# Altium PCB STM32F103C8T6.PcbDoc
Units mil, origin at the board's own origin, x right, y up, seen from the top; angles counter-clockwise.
Board outline 2362.2 x 2362.2 mil, 2 copper layers (Top Layer, Bottom Layer); 70 components, 56 nets, 271 pads, 82 vias.
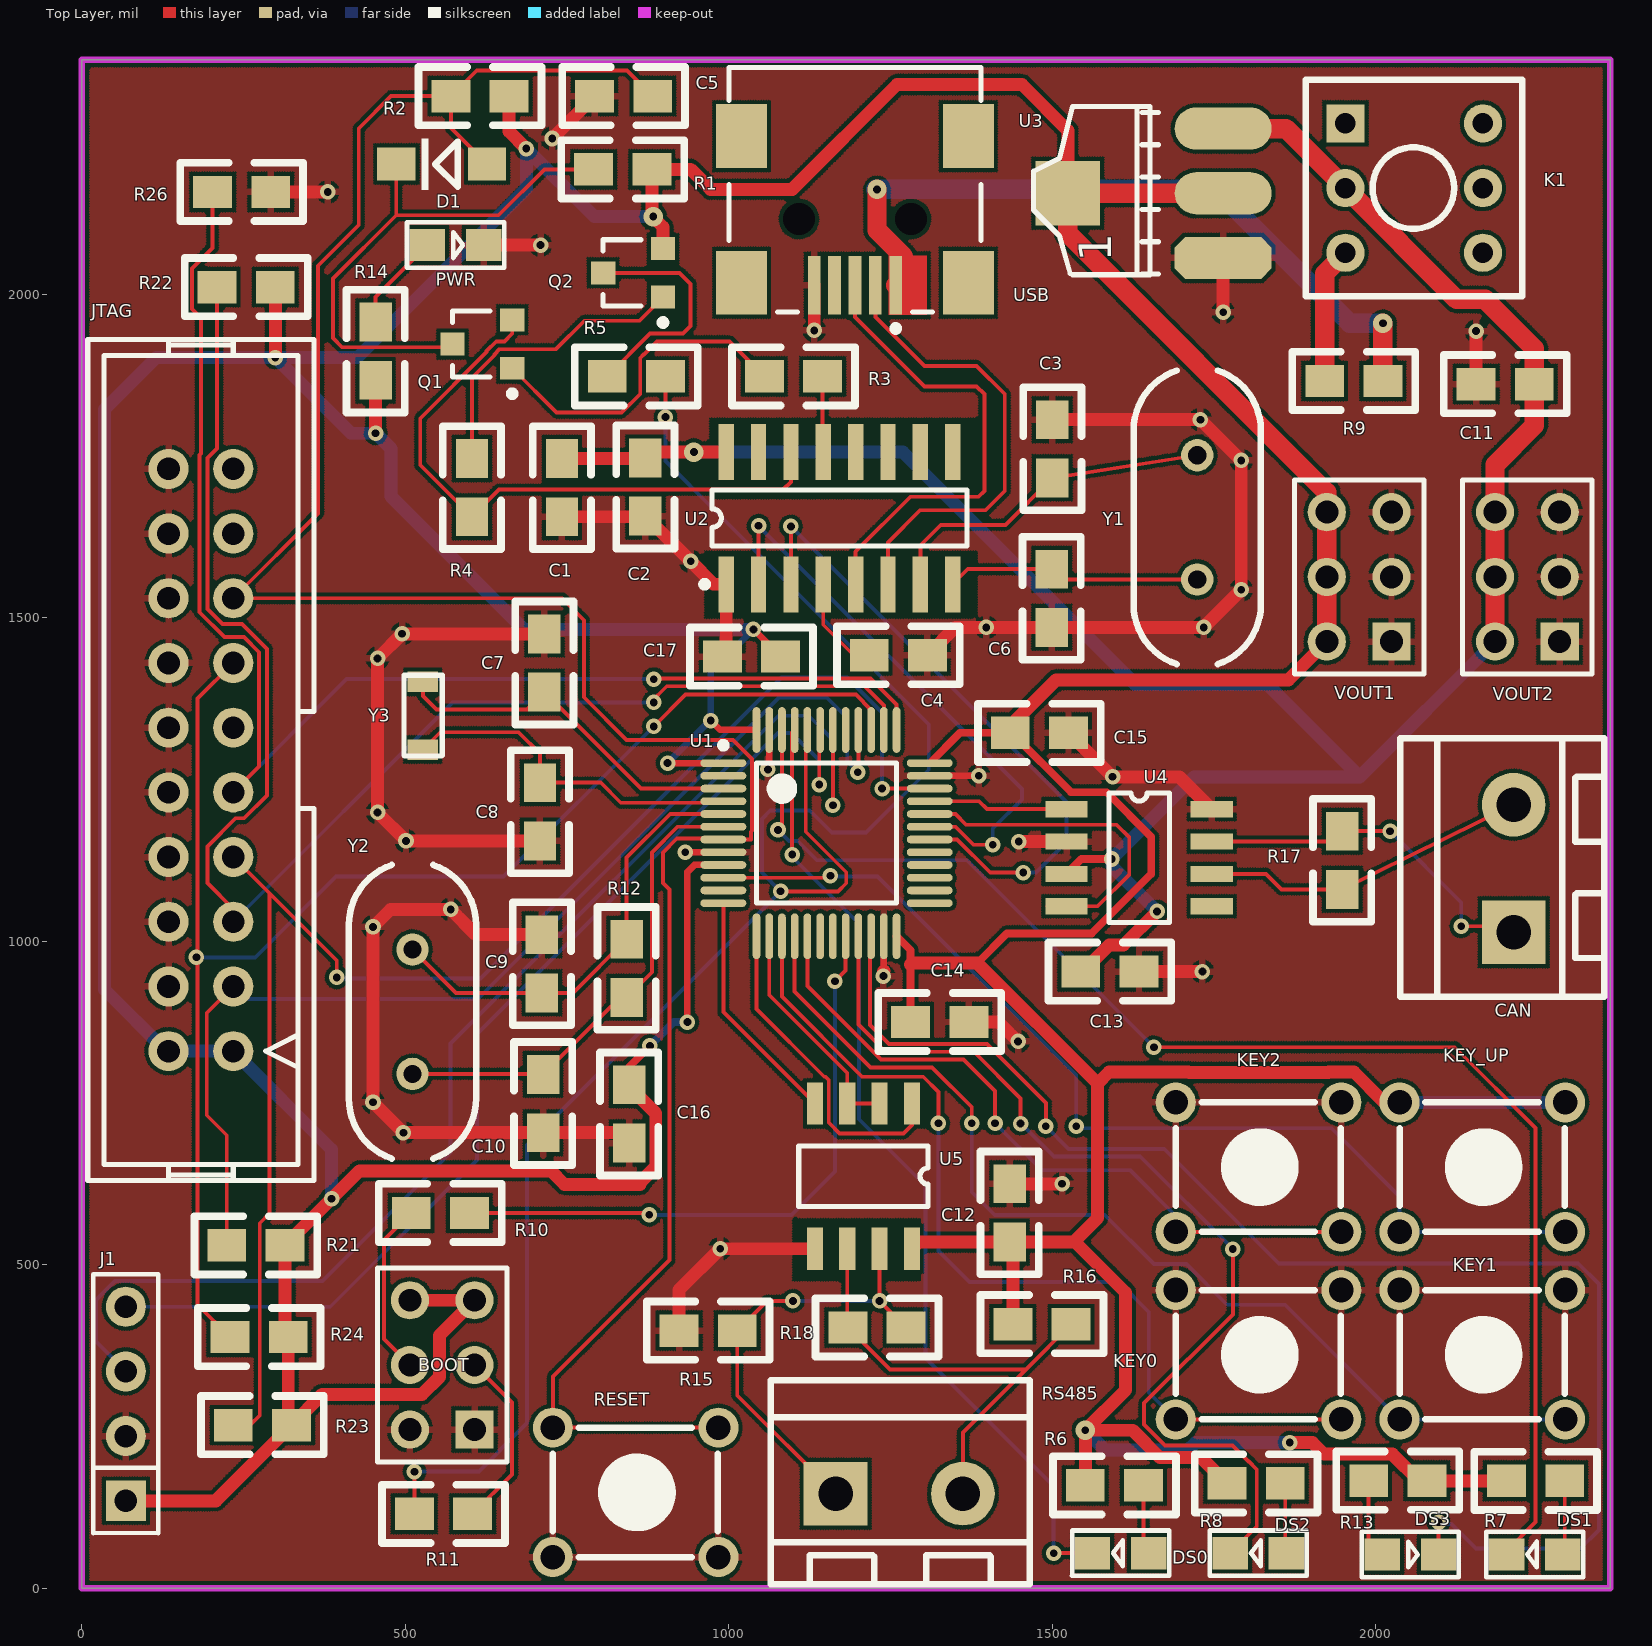
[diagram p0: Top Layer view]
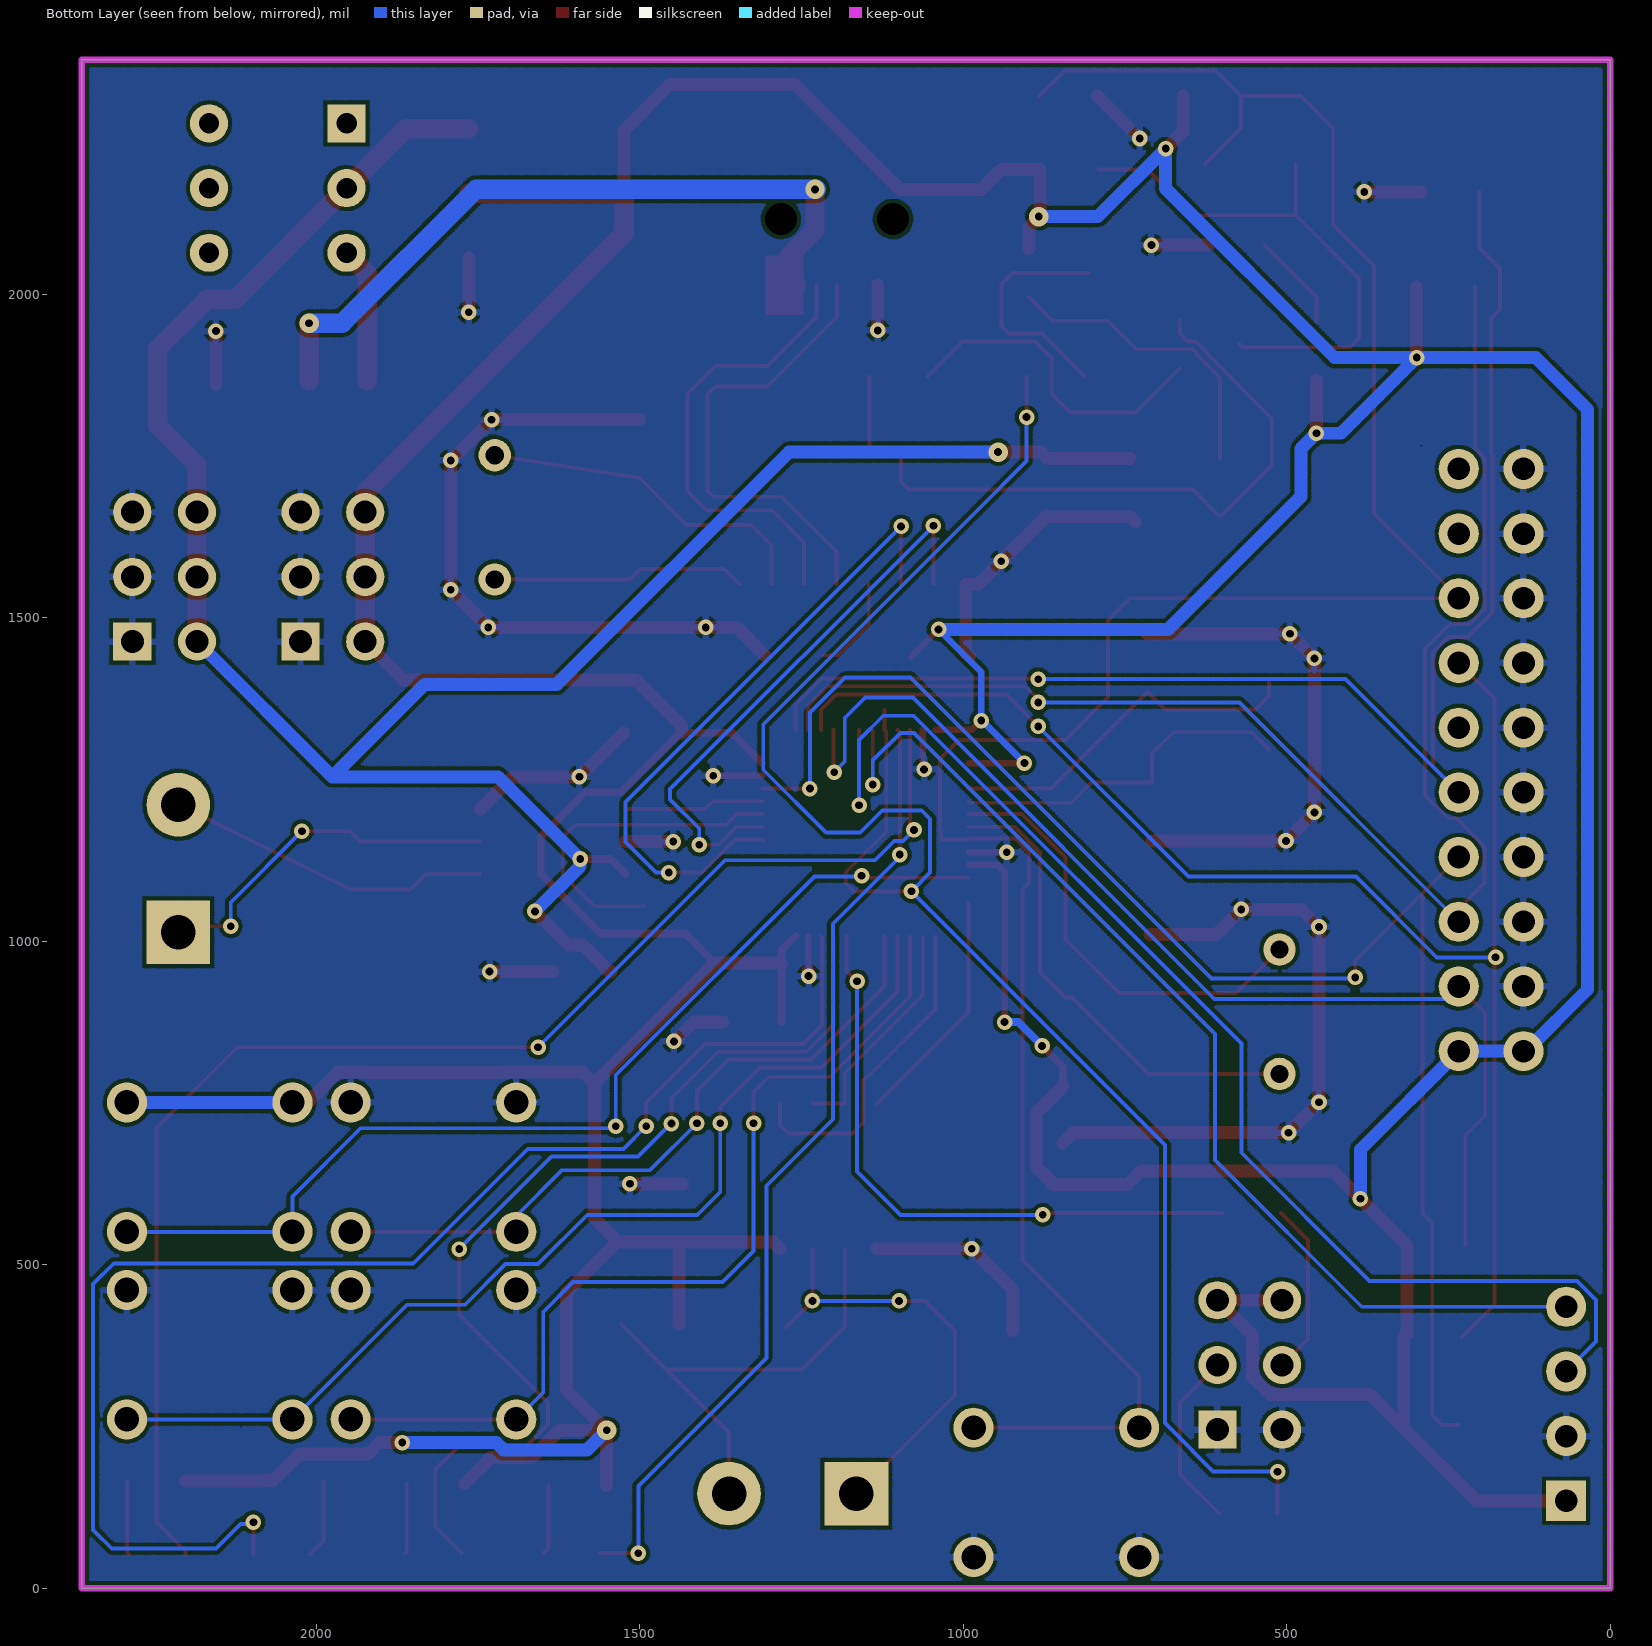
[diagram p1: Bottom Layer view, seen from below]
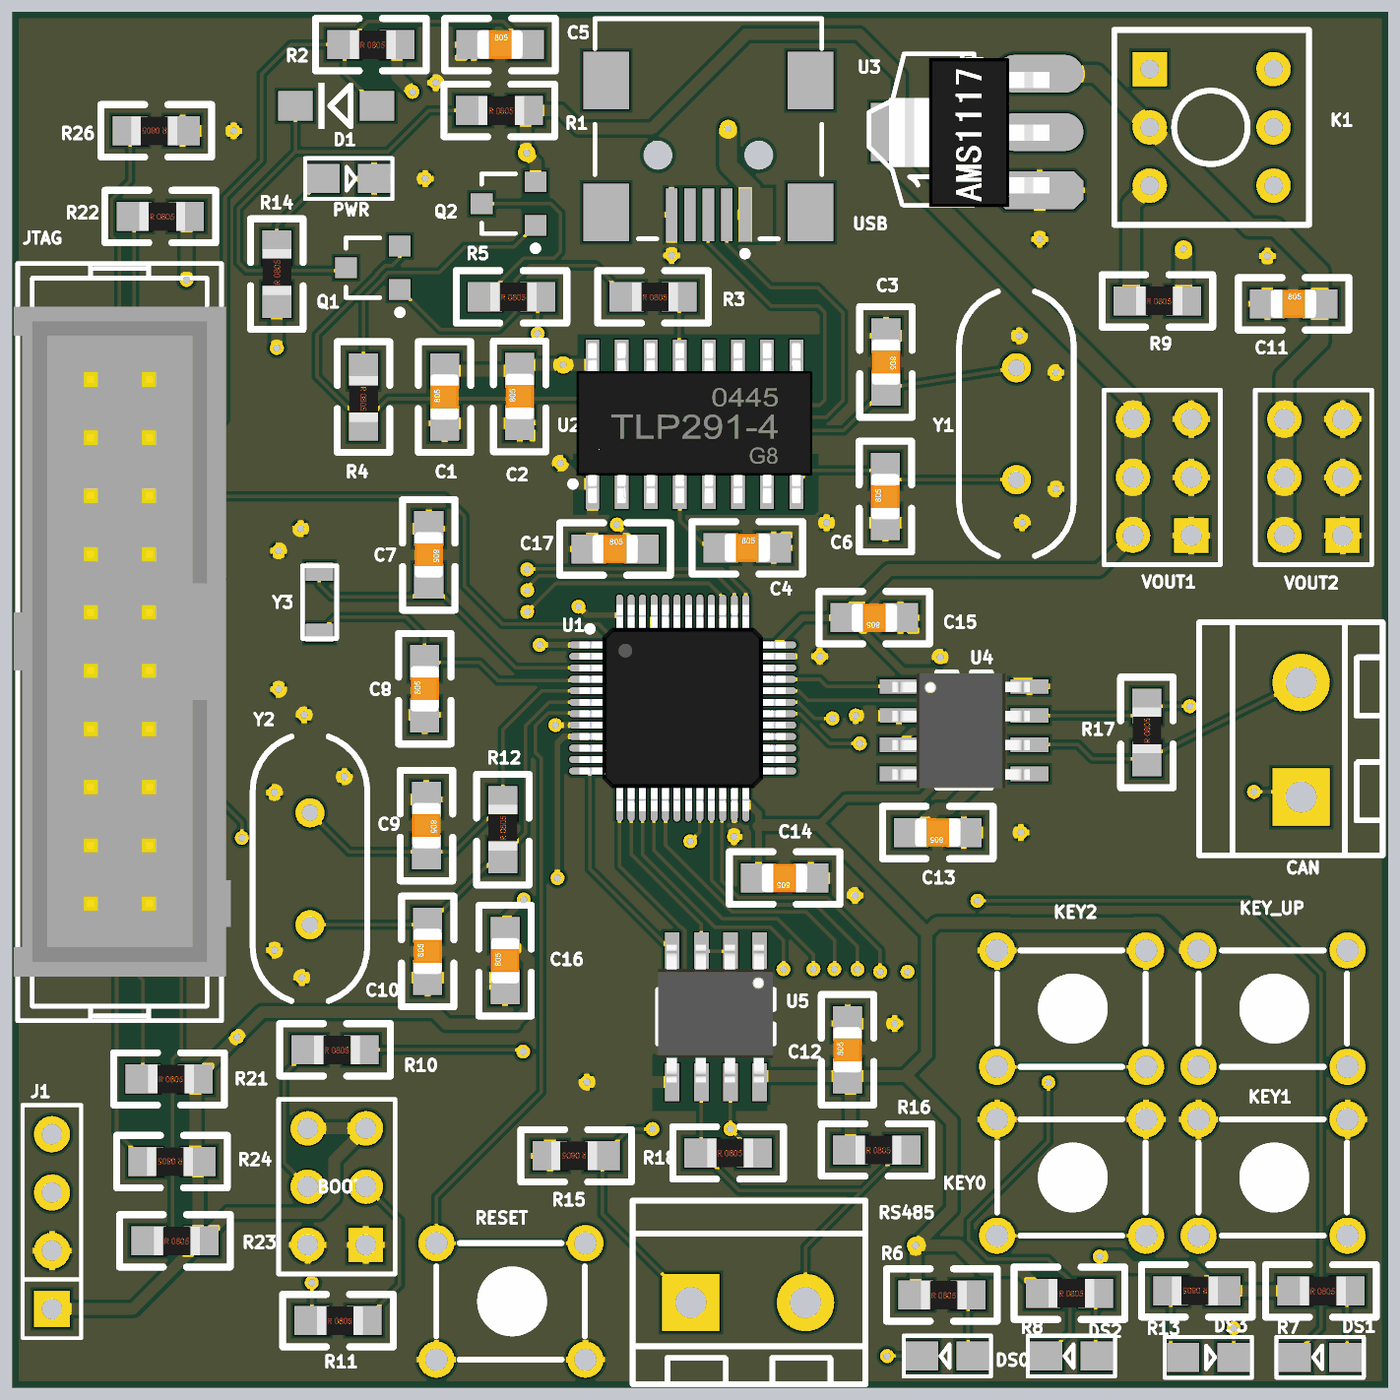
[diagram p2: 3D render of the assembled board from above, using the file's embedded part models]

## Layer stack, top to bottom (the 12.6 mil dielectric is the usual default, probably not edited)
Top Layer: signal copper 1.4
Dielectric: dielectric 12.6, FR-4, Dk 4.8
Bottom Layer: signal copper 1.4

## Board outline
0,0 2362.2,0 2362.2,2362.2 0,2362.2

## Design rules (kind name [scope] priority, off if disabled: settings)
Clearance [All] p1: gap=6
DiffPairsRouting [All] p1: maxlimit=6 minlimit=6 mostfreqgap=6 maxuncoupledlength=500
HoleToHoleClearance [All] p1: gap=5 allowstackedmicrovias=TRUE
MinimumSolderMaskSliver [All] p1: minsoldermaskwidth=2
PolygonConnect [All] p1: connectstyle=Relief reliefconductorwidth=10 reliefentries=4 polygonreliefangle="90 Angle"
RoutingVias [All] p1: holewidth=12 width=24 viastyle="Through Hole" minholewidth=12 minwidth=24 maxholewidth=12 maxwidth=24
SMDNeckDown [All] p1: percent=100.000
SilkToSilkClearance [All] p1: silktosilkclearance=2
SilkscreenOverComponentPads [All] p1: minsilkscreentomaskgap=2
SolderMaskExpansion [All] p1: expansion=2.5
Width PWR [InNetClass('PWR')] p1: maxlimit=60 minlimit=10 preferedwidth=10
Width [All] p2: maxlimit=6 minlimit=6 preferedwidth=6
23 further rules are at their usual default settings.

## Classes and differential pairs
net class GND: GND
net class PWR: GND VCC3.3 VCC5 VUSB

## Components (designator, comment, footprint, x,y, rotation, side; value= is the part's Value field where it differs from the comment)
BOOT "Header 3X2" HDR2X3 607,245 r90 top
C1 "Cap" 0805 742,1656 r90 top
C2 "Cap" 0805 871,1657 r90 top
C3 "Cap" 0805 1500,1806 r270 top
C4 "Cap" 0805 1217,1442 r0 top
C5 "Cap" 0805 792.41,2306.15 r0 top
C6 "Cap" 0805 1499,1485 r90 top
C7 "Cap" 0805 715,1475 r270 top
C8 "Cap" 0805 708,1155 r90 top
C9 "Cap" 0805 711,1010 r270 top
C10 "Cap" 0805 713,704 r90 top
C11 "Cap" 0805 2155,1861 r0 top
C12 "Cap" 0805 1434,535 r90 top
C13 "Cap" 0805 1634,953 r180 top
C14 "Cap" 0805 1371,875 r180 top
C15 "Cap" 0805 1525,1322 r180 top
C16 "Cap" 0805 846,688 r90 top
C17 "Cap" 0805 990,1440 r0 top
CAN "CAN" HEAD2L-0.8 2213,1014 r90 top
D1 "1N4148" DIODE_SOP 626,2201 r180 top
DS0 "LED1" SMDLED 1649,54 r180 top
DS1 "LED1" SMDLED 2289,52 r180 top
DS2 "LED1" SMDLED 1862,54 r180 top
DS3 "LED1" SMDLED 2010,52 r0 top
J1 "OLED_MODBLE" HEAD4 68,135 r90 top
JTAG "JTAG" JTAG_20 184,1280 r90 top
K1 "BUTTON" BTN8.5*8.5 1953,2264 r0 top
KEY0 "KEY_M" KEY_M 1690.83,460.76 r0 top
KEY1 "KEY_M" KEY_M 2036.73,460.76 r0 top
KEY2 "KEY_M" KEY_M 1690.83,750.76 r0 top
KEY_UP "KEY_M" KEY_M 2036.73,750.76 r0 top
PWR "LED1" SMDLED 534,2076 r0 top
Q1 "S8050" SOT-23R 624,1923 r90 top
Q2 "S8550" SOT-23R 857,2033 r90 top
R1 "Res2" R0805 791,2192.94 r0 top
R2 "Res2" R0805 570.41,2306.09 r0 top
R3 "Res2" R0805 1055,1872.94 r0 top
R4 "Res2" R0805 602.94,1746 r270 top
R5 "Res2" R0805 812,1872.94 r0 top
R6 "Res2" R0805 1551,158.94 r0 top
R7 "Res2" R0805 2202,165.94 r0 top
R8 "Res2" R0805 1770,161.94 r0 top
R9 "Res2" R0805 1921,1865.94 r0 top
R10 "Res2" R0805 509,579.94 r0 top
R11 "Res2" R0805 514,114.94 r0 top
R12 "Res2" R0805 842.06,913 r90 top
R13 "Res2" R0805 2079,166.06 r180 top
R14 "Res2" R0805 454.06,1867 r90 top
R15 "Res2" R0805 1013,398.06 r180 top
R16 "Res2" R0805 1439,407.94 r0 top
R17 "Res2" R0805 1948.06,1080 r90 top
R18 "Res2" R0805 1184,402.94 r0 top
R21 "Res2" R0805 224,529.94 r0 top
R22 "Res2" R0805 209,2010.94 r0 top
R23 "Res2" R0805 234,251.94 r0 top
R24 "Res2" R0805 319,388.06 r180 top
R26 "Res2" R0805 292,2158.06 r180 top
RESET "KEY_M" KEY_M 728,248 r0 top
RS485 "RS485" HEAD2L-0.8 1165,146 r0 top
U1 "STM32F103C8T6" LQFP48_N 1151,1167 r0 top
U2 "CH340G" SOP16M 1171,1654 r0 top
U3 "AMS1117-3.3" AMS1117 1764,2056 r90 top
U4 "TJA1050" SOP-8 1522,1204 r0 top
U5 "SP3485" SOP-8 1283,749 r270 top
USB "USB" USB/SM0.8-6H5 1195,2323 r90 top
VOUT1 "Header 3X2" HDR2X3 2024.25,1463.09 r90 top
VOUT2 "Header 3X2" HDR2X3 2284.25,1463.09 r90 top
Y1 "8M" XTAL_US 1724,1559 r90 top
Y2 "8M" XTAL_US 511,987 r270 top
Y3 "32.768k" 32.768K晶振 557,1411 r270 top

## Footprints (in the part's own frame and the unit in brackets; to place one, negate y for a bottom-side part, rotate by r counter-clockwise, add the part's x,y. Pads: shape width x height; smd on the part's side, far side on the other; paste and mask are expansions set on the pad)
32.768K晶振 [mil]
  rect 31.5x47.24 smd: 1(10,-30) 2(115,-30)
  silkscreen extent 0,-59 125,0
0805 [mil]
  rect 60x50 smd: 1(0,-0.06) 2(90,-0.06)
  silkscreen extent -50,-45 140,45, body extent 6,-25 84,25, height 31
AMS1117 [mil]
  oct 65x150 smd: 1(0.03,-0.06)
  oval 65x150 smd: 2(100.03,-0.06) 3(200.03,-0.06)
  rect 100x100 smd: 4(100.03,239.94)
  silkscreen extent -26,100 234,293, body extent -29,-17 227,259, height 73
BTN8.5*8.5 [mm]
  rect 1.5x1.5 hole 0.8: 1(0,0)
  round 1.5 hole 0.8: 2(0,-2.54) 3(0,-5.08) 4(5.4,-5.08) 5(5.4,-2.54) 6(5.4,0)
  silkscreen extent -1.55,-6.79 6.95,1.71
DIODE_SOP [mm]
  rect 1.5x1.3 smd: 1(0,0) 2(3.556,0)
  silkscreen extent 1.14,-1.02 2.56,1.02
HDR2X3 [mm]
  rect 1.5x1.5 hole 0.9: 1(0,0)
  round 1.5 hole 0.9: 2(0,2.54) 3(2.54,0) 4(2.54,2.54) 5(5.08,0) 6(5.08,2.54)
  silkscreen extent -1.27,-1.27 6.35,3.81
HEAD2L-0.8 [mm]
  rect 2.5x2.5 hole 1.35: 1(0,0)
  round 2.5 hole 1.35: 2(5,0)
  silkscreen extent -2.54,-3.56 7.62,4.44
HEAD4 [mil]
  rect 62x62 hole 35: 1(0,0)
  round 62 hole 35: 2(100,0) 3(200,0) 4(300,0)
  silkscreen extent -50,-50 350,51
JTAG_20 [mil]
  round 62 hole 35: 1(-450,-50) 2(-450,50) 3(-350,-50) 4(-350,50) 5(-250,-50) 6(-250,50) 7(-150,-50) 8(-150,50) 9(-50,-50) 10(-50,50) 11(50,-50) 12(50,50) 13(150,-50) 14(150,50) 15(250,-50) 16(250,50) 17(350,-50) 18(350,50) 19(450,-50) 20(450,50)
  silkscreen extent -650,-175 650,175, body extent -574,-191 576,182, height 350
KEY_M [mil]
  round 62 hole 38: 1(0,0) 1(255.91,0) 2(0,-200) 2(255.91,-200)
  silkscreen extent 0,-200 255,0
LQFP48_N [mm]
  oval 1.8x0.3 smd: 1(-4.05,2.75) 2(-4.05,2.25) 3(-4.05,1.75) 4(-4.05,1.25) 5(-4.05,0.75) 6(-4.05,0.25) 7(-4.05,-0.25) 8(-4.05,-0.75) 9(-4.05,-1.25) 10(-4.05,-1.75) 11(-4.05,-2.25) 12(-4.05,-2.75) 25(4.05,-2.75) 26(4.05,-2.25) 27(4.05,-1.75) 28(4.05,-1.25) 29(4.05,-0.75) 30(4.05,-0.25) 31(4.05,0.25) 32(4.05,0.75) 33(4.05,1.25) 34(4.05,1.75) 35(4.05,2.25) 36(4.05,2.75)
  oval 0.3x1.8 smd: 13(-2.75,-4.05) 14(-2.25,-4.05) 15(-1.75,-4.05) 16(-1.25,-4.05) 17(-0.75,-4.05) 18(-0.25,-4.05) 19(0.25,-4.05) 20(0.75,-4.05) 21(1.25,-4.05) 22(1.75,-4.05) 23(2.25,-4.05) 24(2.75,-4.05) 37(2.75,4.05) 38(2.25,4.05) 39(1.75,4.05) 40(1.25,4.05) 41(0.75,4.05) 42(0.25,4.05) 43(-0.25,4.05) 44(-0.75,4.05) 45(-1.25,4.05) 46(-1.75,4.05) 47(-2.25,4.05) 48(-2.75,4.05)
  silkscreen extent -4.17,-2.75 2.75,3.57, body extent -4.5,-4.5 4.5,4.5, height 1.5
R0805 [mil]
  rect 60x50 smd: 1(0,0) 2(90,0)
  silkscreen extent -50,-45 140,45, body extent 9,-25 88,25, height 15
SMDLED [mm]
  rect 1.4x1.27 smd: 1(0.001,-0.002) 2(2.211,-0.002)
  silkscreen extent -0.8,-0.89 3.01,0.89
SOP16M [mm]
  rect 0.6x2.2 smd: 1(-4.445,-2.6) 2(-3.175,-2.6) 3(-1.905,-2.6) 4(-0.635,-2.6) 5(0.635,-2.6) 6(1.905,-2.6) 7(3.175,-2.6) 8(4.445,-2.6) 9(4.445,2.6) 10(3.175,2.6) 11(1.905,2.6) 12(0.635,2.6) 13(-0.635,2.6) 14(-1.905,2.6) 15(-3.175,2.6) 16(-4.445,2.6)
  silkscreen extent -5.42,-2.72 5,1.1, body extent -5.15,-3.45 5.15,3.55, height 2.1
SOP-8 [mil]
  rect 65x25 smd: 1(0,0) 2(0,-50) 3(0,-100) 4(0,-150) 5(224.41,-150) 6(224.41,-100) 7(224.41,-50) 8(224.41,0)
  silkscreen extent 65,-175 159,25, body extent -11,-174 225,22, height 71
SOT-23R [mm]
  rect 0.9x0.95 smd: 1(0.95,-1.048) 2(-0.95,-1.048) 3(0,1.302)
  silkscreen extent -2.07,-1.17 1.3,1.3
USB/SM0.8-6H5 [mm]
  rect 2.3x0.5 smd: 1(-7.85,-1.6) 2(-7.85,-0.8) 3(-7.85,0) 4(-7.85,0.8) 5(-7.85,1.6)
  rect 2.5x2 smd: 6(-7.75,4.45) 7(-1.996,4.45) 8(-7.75,-4.45) 9(-1.996,-4.45)
  round 0.6 hole 1.27 unplated: MH1(-5.25,2.2) MH2(-5.25,-2.2)
  silkscreen extent -9.67,-4.95 0.7,4.95
XTAL_US [mil]
  round 50 hole 28: 1(0,0) 2(192.13,0)
  silkscreen extent -131,-98 323,98

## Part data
BOOT VOUT1 VOUT2: "Header, 3-Pin, Dua"
C1 C2 C3 C4 C5 C6 C7 C8 C9 C10 C11 C12 C13 C14 C15 C16 C17: "Capacitor"
DS0 DS1 DS2 DS3 PWR: library part LED2, "Typical RED, GREEN, YELLOW, AMBER GaA"
J1: library part OLED_MOD
K1: library part B
Q1: library part NPN, "8050/BCW846/B"
Q2: library part PNP, "8550/"
R1 R2 R3 R4 R5 R6 R7 R8 R9 R10 R11 R12 R13 R14 R15 R16 R17 R18 R21 R22 R23 R24 R26: "Resistor"
U1: library part STM32F10
U2: "USB"
U3: library part AM
U4: library part SN65HV
U5: library part MA
Y1 Y2: library part XTAL, "Crystal Oscil"
Y3: library part XTAL, "Crystal"

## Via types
v1: diameter 24, hole 12, Top Layer to Bottom Layer, 77 vias
v2: diameter 30, hole 12, Top Layer to Bottom Layer, 5 vias

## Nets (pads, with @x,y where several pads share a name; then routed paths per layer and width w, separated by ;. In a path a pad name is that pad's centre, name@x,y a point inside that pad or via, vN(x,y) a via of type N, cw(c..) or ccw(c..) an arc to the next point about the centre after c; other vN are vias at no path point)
BOOT0: R5.2 R11.1 U1.44 | length 2874.7
  Top Layer w6: R11.1 v1(514,180) ; v1(902,1810) R5.2 ; v1(1080,1077) 1169,1077 1181.5,1089.5 1181.5,1106.5 1118.84,1169.16 1118.84,1323.82 U1.44 U1.44@1121.47,1357.37
  Bottom Layer w6: v1(514,180) 613.78,180 645.53,211.74 645.53,212.53 688,255 688,685 v1(1080,1077) 1051,1106 1051,1189 1064,1202 1125,1202 1159,1168 1212,1168 1309,1265 1309,1335 978,1666 902,1742 v1(902,1810)
BOOT1: R10.2 U1.20 | length 968
  Top Layer w6: R10.2 v1@879,579.94 ; v1(1164,938) 1180.53,954.53 U1.20
  Bottom Layer w6: v1@875,575 v1(877,577) 1097,577 1164,644 v1(1164,938)
CAN_RX: U1.32 U4.4 | length 527.3
  Top Layer w6: U1.32 1350.1,1196.53 1366.63,1180 1599,1180 1619,1160 1619,1103 1570,1054 U4.4 U4.4@1492.63,1054
CAN_TX: U1.33 U4.1 | length 216.6
  Top Layer w6: U1.33 1386.79,1216.21 1399,1204 U4.1
CH340_D+: U2.5 USB.3 | length 736.4
  Top Layer w6: USB.3 1195,1964.8 1302.29,1857.5 1383,1857.5 1395,1845.5 1395,1696 1386,1687 1281,1687 1196,1602 U2.5
CH340_D-: U2.6 USB.2 | length 726.4
  Top Layer w6: USB.2 1226.5,1964.8 1302.29,1889 1383,1889 1426.5,1845.5 1426.5,1696 1396.5,1666 1295.5,1666 1246,1616.5 U2.6
GND: BOOT.1 BOOT.2 C1.1 C2.1 C3.1 C4.2 C5.1 C6.1 C7.1 C8.1 C9.1 C10.1 C11.1 C12.2 C13.1 C14.1 C15.1 C16.1 C17.1 J1.2 JTAG.4 JTAG.6 JTAG.8 JTAG.10 JTAG.12 JTAG.14 JTAG.16 JTAG.18 JTAG.20 KEY0.1 KEY1.1 KEY2.1 PWR.2 R15.2 R26.1 RESET.2 U1.8 U1.23 U1.35 U1.47 U2.1 U3.1 U4.2 U4.8 U5.5 USB.5 VOUT1.1 VOUT1.3 VOUT1.5 VOUT2.1 VOUT2.3 VOUT2.5 | length 4911.3
  Top Layer w10: v1(932.47,1137.47) U1.8 ; v1@1058,1263 v1(1060.42,1265.42) 1062.42,1265.42 U1.47 ; v1@1239.58,953.58 U1.23 ; U1.35 v1(1386.42,1255.58)
  Top Layer w20: R26.1 v1(379.94,2158.06) ; PWR.2 v1(708.98,2075.94) ; C8.1@707.94,1155 v1(501,1155) v1(457,1199) v1(457,1437) v1(495,1475) C7.1@715.06,1475 ; C9.1 609,1010 v1(570,1049) 477,1049 v1(450,1022) v1(450,751) v1(497,704) C10.1 830.06,704 C16.1 ; v1(727,2240.68) C5.1 ; C1.1@733.94,1647.87 C1.1 870.06,1656 C2.1 v1(941,1587.06) 976.43,1551.64 U2.1 996,1445.94 C17.1 ; R15.2 923,461 v1(986.59,524.59) U5.5 ; v1(1132.01,1943.99) USB.5 ; v1(1239,946) 1239,953 v1@1239.58,953.58 ; C4.2 1350.06,1485 C6.1 v1(1734,1485) v1(1792,1543) v1(1792,1743) v1(1729,1806) C3.1 ; C14.1 1416.94,875.06 v1(1447,845) ; C12.2 v1(1515,625) v1@1514,626 ; v1(1448,1154) U4.2 ; C15.1 v1(1593.06,1254) 1696.41,1254 U4.8 ; C13.1 v1(1732.06,953.06) ; v1(1764.06,1971.94) U3.1 ; C11.1 v1(2155,1943)
  other v1: 1398,1485
JTCK: JTAG.9 R26.2 U1.37 | length 2176.5
  Top Layer w6: R26.2 202,2071.66 170,2039.66 170,1976.94 184,1962.94 184,1753.54 182,1751.54 182,1508.46 220.46,1470 250.57,1470 274,1446.57 274,1270 JTAG.9 ; v1@882,1405 883,1406 956.21,1406 956.27,1405.94 1023.73,1405.94 1023.79,1406 1046.21,1406 1046.27,1405.94 1113.73,1405.94 1113.79,1406 1219,1406 1259.27,1365.73 U1.37
  Bottom Layer w6: JTAG.9 409,1405 v1(884,1405)
JTDI: JTAG.5 R22.1 U1.38 | length 2316.8
  Top Layer w6: R22.1 209,1761.57 194,1746.57 194,1513.43 217.43,1490 247.54,1490 286,1451.54 286,1225.43 250.57,1190 237.43,1190 194,1146.57 194,1090 234,1050 JTAG.5 ; v1@879.12,1369 904.12,1394 951.24,1394 951.3,1393.94 1028.7,1393.94 1028.76,1394 1041.24,1394 1041.3,1393.94 1118.7,1393.94 1118.76,1394 1210,1394 1222,1382 1239.58,1364.42 U1.38
  Bottom Layer w6: JTAG.5 573,1369 v1(884,1369)
JTDO: JTAG.13 R24.2 U1.39 | length 2337.2
  Top Layer w6: R24.2 179,438.06 179,1375 JTAG.13 ; v1(884,1332) 933,1381 1196.27,1381 1219.9,1357.37 U1.39
  Bottom Layer w6: v1(177,975) 268,975 393,1100 652,1100 v1(884,1332)
JTMS: JTAG.7 R23.1 U1.34 | length 2363.1
  Top Layer w6: R23.1 259.94,251.94 275,267 275,563.94 290,578.93 290,1074 ; JTAG.7 290,1074 ; v1(394,944) 394,970 290,1074 ; v1@1236,1235 v1(1236.9,1235.9) U1.34
  Bottom Layer w6: v1@394.1,942.1 616.1,942.1 1081.6,1407.6 1182.6,1407.6 1236.9,1353.31 v1(1236.9,1235.9)
JTRST: JTAG.3 R21.1 U1.40 | length 1749
  Top Layer w6: R21.1 224,700 193,731 193,889 JTAG.3 ; v1(1199.43,1261) 1200.21,1261.79 U1.40
  Bottom Layer w6: JTAG.3 253.16,910.84 611.84,910.84 1077.34,1376.34 1151.34,1376.34 1183,1344.68 1183,1277.43 v1(1199.43,1261)
KEY0: KEY0.2 U1.15 | length 1445.1
  Top Layer w6: U1.15 1082.1,914.22 1205.82,790.5 1300.5,790.5 1324,767 v1@1324,719 ; KEY0.2@1690.83,260.76 KEY0.2@1946.73,260.76
  Bottom Layer w6: v1(1324,718.5) 1324,521 1372,473 1603,473 1649,427 1649,302.58 KEY0.2@1690.83,260.76
KEY1: KEY1.2 U1.16 | length 1625.8
  Top Layer w6: U1.16 1101.79,922.37 1219.16,805 1313.84,805 1375.42,743.42 v1@1375.42,719.42
  Bottom Layer w6: v1(1375.42,718.5) 1375.42,612.58 1411,577 1581,577 1657.24,500.76 1707.39,500.76 1770.15,438 1859.49,438 2036.73,260.76 KEY1.2@2292.64,260.76
KEY2: KEY2.2 U1.17 | length 1103.2
  Top Layer w6: U1.17 1121.47,930.53 1235,817 1363,817 1411.5,768.5 v1(1411.5,718.5) ; KEY2.2@1690.83,550.76 KEY2.2@1946.73,550.76
  Bottom Layer w6: v1(1411.5,718.5) 1484,646 1620,646 1690.83,575.17 KEY2.2@1690.83,550.76
LED0: DS0.2 U1.45 | length 1501.3
  Top Layer w6: v1(1097.84,1133.84) 1097.84,1322.51 U1.45 ; v1(1502.06,54.06) DS0.2
  Bottom Layer w6: v1(1097.84,1133.84) 1097.84,1130.46 1201.3,1027 1201.3,724.7 1304,622 1304,356 1502.06,157.94 v1(1502.06,54.06)
LED1: DS1.2 U1.46 | length 2207
  Top Layer w6: v1@1079,1175 v1(1076,1172) 1080.21,1172 1082.1,1170.1 U1.46 ; v1(1657,836) 2122,836 2247,711 2247,102 2201.96,56.96 DS1.2
  Bottom Layer w6: v1(1076,1172) 1093.16,1154.84 1106.54,1154.84 1136.38,1125 1368,1125 v1(1657,836)
LED2: DS2.2 U1.21 | length 1558.9
  Top Layer w6: U1.21 1200.21,871.15 1242.37,829 1379,829 1451,757 v1(1451,718) ; DS2.2 1816,95.11 1816,183.66 1803.73,195.94 1803.06,195.94 1778.24,220.76 1674.26,220.76 1642,253.01 1642,286 1779,423 v1(1779,524)
  Bottom Layer w6: v1(1451,718) 1451.7,718 1502.7,667 1636,667 v1(1779,524)
LED3: DS3.2 U1.22 | length 2158.9
  Top Layer w6: U1.22 1218,1005.65 1218,870.34 1247.34,841 1399,841 1490,750 v1(1490,714) ; DS3.2 v1(2097.04,101.96)
  Bottom Layer w6: v1(1490,714) 1525,679 1673,679 1850,502 2313,502 2345,470 2345,90 2316,61 2154.97,61 2116.86,99.11 2099.89,99.11 v1(2097.04,101.96)
NetBOOT_3: BOOT.3 R11.2 | length 279.4
  Top Layer w6: R11.2 665,175.93 665,287 BOOT.3
NetBOOT_4: BOOT.4 R10.1 | length 268.9
  Top Layer w6: BOOT.4 467,385 467,537.93 R10.1
NetC3_2: C3.2 U2.7 Y1.2 | length 534.2
  Top Layer w6: U2.7 1296,1612 1327.5,1643.5 1427.44,1643.5 C3.2 Y1.2
NetC4_1: C4.1 U2.4 | length 153.1
  Top Layer w6: U2.4 1146,1489 1193.06,1441.94 C4.1
NetC6_2: C6.2 U2.8 Y1.1 | length 394.3
  Top Layer w6: U2.8 1369.36,1575 C6.2 1515.06,1559 Y1.1
NetCAN_1: CAN.1 R17.2 U4.7 | length 559.5
  Top Layer w6: U4.7 1932.06,1154 R17.2 v1(2022,1170) ; v1(2132,1023) 2204,1023 CAN.1
  Bottom Layer w6: v1(2022,1170) 2132,1060 v1(2132,1023)
NetCAN_2: CAN.2 R17.1 U4.6 | length 551.2
  Top Layer w6: U4.6 1830,1104 1854,1080 R17.1 CAN.2 CAN.2@2168.85,1210.85
NetD1_2: D1.2 Q1.3 R1.1 | length 836.6
  Top Layer w6: D1.2 486,2122 ; Q1.3 567.74,1918 402,1918 388,1932 388,2024 486,2122 ; R1.1 714.94,2192.94 644,2122 486,2122
NetDS0_1: DS0.1 R6.2 | length 108.2
  Top Layer w6: R6.2 1641,62.03 DS0.1
NetDS1_1: DS1.1 R7.2 | length 115.1
  Top Layer w6: DS1.1 2292,55.1 R7.2
NetDS2_1: DS2.1 R8.2 | length 108.7
  Top Layer w6: R8.2 1860,56.03 DS2.1
NetDS3_1: DS3.1 R13.2 | length 122.8
  Top Layer w6: R13.2 1989,72.97 DS3.1
NetK1_3: K1.3 R9.1 | length 211.3
  Top Layer w30: R9.1 1921,2032 K1.3
NetPWR_1: PWR.1 R14.2 | length 152.1
  Top Layer w6: R14.2 454.06,1995.97 PWR.1
NetQ1_1: Q1.1 R4.2 U2.14 | length 965.5
  Top Layer w6: Q1.1 665.26,1939.26 653,1927 640.55,1927 625.56,1912.01 625.56,1910.53 523,1807.97 523,1735.94 R4.2 644.94,1698 1084,1698 1096,1710 U2.14
NetQ1_2: Q1.2 R3.1 | length 518.7
  Top Layer w6: Q1.2 733.86,1817 834,1817 863,1846 863,1901.66 868.27,1906.94 868.94,1906.94 889,1927 1000.94,1927 R3.1
NetQ2_2: Q2.2 R4.1 | length 472.8
  Top Layer w6: R4.1 602.94,1870.94 637.56,1905.56 637.56,1907.04 645.52,1915 733,1915 777,1959 861.66,1959 Q2.2
NetQ2_3: Q2.3 R5.1 | length 368.6
  Top Layer w6: Q2.3 924,2033 941,2016 941,1951 929,1939 878.07,1939 R5.1
NetR3_2: R3.2 U2.13 | length 117
  Top Layer w6: R3.2 1145,1757.36 U2.13
NetR15_1: R15.1 R18.2 RS485.1 U5.7 | length 692.7
  Top Layer w6: v1(1099.06,443.94) 1058.87,443.94 R15.1 1013,298 RS485.1 ; U5.7 v1(1233,443.94) R18.2
  Bottom Layer w6: v1(1099.06,443.94) v1(1233,443.94)
NetR16_2: R16.2 R18.1 RS485.2 U5.6 | length 755.2
  Top Layer w6: U5.6 1183,403.94 R18.1 1248.94,338 1459.07,338 ; RS485.2 1361.85,240.79 1459.07,338 ; R16.2 1459.07,338
NRST: C5.2 D1.1 JTAG.15 R2.1 RESET.1 U1.7 | length 3911.6
  Top Layer w6: D1.1 570.41,2256.59 R2.1 ; C5.2 842.5,2346 610.32,2346 R2.1 ; RESET.1@983.91,248 728,248 728,327 908,507 908,1080 898,1090 898,1137 919.47,1158.47 990.23,1158.47 U1.7 1034.16,1157.16 1034.16,1168.84 1035.98,1170.67 1035.98,1281.44 1006.42,1311 842,1311 776,1377 776,1496 742,1530 JTAG.15 365,1661 365,2044 428,2107 428,2256 478.09,2306.09 R2.1
OLED_SCL: J1.3 U1.42 | length 1974.5
  Top Layer w6: v1(1160.84,1210) U1.42
  Bottom Layer w6: J1.3 22,381 22,445.57 51.43,475 372,475 570,673 570,842 1076.5,1348.5 1123.5,1348.5 1160.84,1311.16 v1(1160.84,1210)
OLED_SDA: J1.4 U1.43 | length 1693.4
  Top Layer w6: v1(1139.84,1242) 1139.84,1325.13 U1.43
  Bottom Layer w6: J1.4 384,435 610.5,661.5 610.5,856.5 1076,1322 1097,1322 1139.84,1279.16 v1(1139.84,1242)
RS485_RE: U1.14 U5.2 U5.3 | length 358.5
  Top Layer w6: U1.14 1062.42,916.58 1183,796 U5.3 U5.2
RS485_RX: U1.12 U5.4 | length 368.3
  Top Layer w6: U1.12 991.55,890.45 U5.4
RS485_TX: U1.13 U5.1 | length 508.9
  Top Layer w6: U1.13 1042.73,895.27 1147.5,790.5 1149.23,790.5 1154.5,785.23 1154.5,719.77 1171.27,703 1270,703 1283,716 U5.1
RXD: U1.30 U2.3 | length 1007.9
  Top Layer w6: U2.3 v1(1096,1641) ; U1.30@1309.13,1155.84 U1.30 1352.84,1157.16 1404,1106 v1(1455,1106)
  Bottom Layer w6: v1(1096,1641) 1522,1215 1522,1153 1475,1106 v1(1455,1106)
TXD: U1.31 U2.2 | length 879.7
  Top Layer w6: U2.2 v1(1046,1642) ; U1.31 1350.16,1176.84 1378,1149 v1(1408,1149)
  Bottom Layer w6: v1(1046,1642) 1453,1235 1453,1219 1408,1174 v1(1408,1149)
VCC3.3: BOOT.5 BOOT.6 C12.1 C14.2 C15.2 C16.2 C17.2 J1.1 JTAG.1 JTAG.2 KEY_UP.1 Q2.1 R1.2 R2.2 R6.1 R7.1 R8.1 R13.1 R14.1 R16.1 R21.2 R22.2 R23.2 R24.1 U1.1 U1.9 U1.24 U1.36 U1.48 U3.2 U3.4 U5.8 VOUT1.2 VOUT1.4 VOUT1.6 | length 13283.8
  Top Layer w10: v1(905.27,1275.27) U1.1 ; v1(936,875) 936,1107 946.79,1117.79 U1.9 ; v1(972,1341) 986.55,1326.45 U1.48 ; v1(1038,1481.94) C17.2
  Top Layer w12: C16.2 846.06,806.06 v1(878,838) ; U1.24 1281,985.82 1281,964 C14.2 ; U1.36 1357.24,1322.06 C15.2 1436.94,1322.06 1529,1230 1584,1230 1653,1161 1653,1104 1561,1012 1430,1012 1384,966
  Top Layer w20: J1.1 207.06,135 R23.2 ; v1(299,1902) R22.2 ; v1(454.06,1785.06) R14.1 ; BOOT.6 BOOT.5 552.53,390.53 552.53,326.14 525.86,299.47 371.54,299.47 R23.2 ; R2.2 660.41,2251.59 v1(687,2225) ; C16.2 846.06,775 887.06,734 887.06,651.37 863,627.31 863,624 746,624 725,645 429.07,645 v1(386,601.93) R21.2 314,393.06 R24.1 319,256.94 R23.2 ; Q2.1 898.26,2103.74 881,2121 R1.2 941.06,2192.94 972,2162 1098,2162 1260,2324 1453,2324 1524.06,2252.94 U3.4 ; 1281,964 1283,966 1384,966 1570,780 ; U5.8 1293.41,535 C12.1 ; C15.2 1435,1333 1506,1404 1865.17,1404 VOUT1.2 ; R16.1 1439,530.06 C12.1 ; R6.1 v2(1551,244) ; R8.1 1730.18,201.76 1666.39,201.76 1624.14,244 v2(1551,244) ; v1(1867,225) 1902,225 1919.94,207.06 2025.63,207.06 2066.63,166.06 R13.1 2079.13,165.94 R7.1 ; KEY_UP.1@2036.73,750.76 2013.2,750.76 1966.2,797.76 1927.26,797.76 1926.51,797 1711.05,797 1710.29,797.76 1587.76,797.76 1570,780 ; C12.1 1535,535 ; 1535,535 1535,537 1570,572 1570,780 ; 1535,535 1613,457 1613,306 v2(1551,244)
  Top Layer w30: U3.2 U3.4 1524.06,2093.94 1924.25,1693.75 VOUT1.6 VOUT1.4 VOUT1.2
  Bottom Layer w10: v1(905.27,1275.27) 971,1341 v1(972,1341) 972,1415.94 v1(1038,1481.94)
  Bottom Layer w12: v1(878,838) 915,875 v1(936,875)
  Bottom Layer w20: v1(386,601.93) 386,678 JTAG.1 JTAG.2 130.4,830 35,925.4 35,1822 115,1902 v1(299,1902) ; v2(883,2120) 792,2120 v1(687,2225) 687,2163 426,1902 v1(299,1902) ; v1(1038,1481.94) 683.06,1481.94 478,1687 478,1761.13 v1(454.06,1785.06) 415.94,1785.06 v1(299,1902) ; v2(1551,244) 1581.24,213.76 1710.29,213.76 1721.54,225 v1(1867,225) ; KEY_UP.1@2036.73,750.76 KEY_UP.1@2292.64,750.76
VCC5: C1.2 C2.2 C11.2 C13.2 K1.2 U2.16 U3.3 U4.3 VOUT2.2 VOUT2.4 VOUT2.6 | length 3672.7
  Top Layer w12: U4.3 1545,1127 v1(1592,1127)
  Top Layer w20: C1.2 870.06,1746 C2.2 880.43,1756.36 U2.16 ; C13.2 1547,953.06 1588,994.06 1610.06,994.06 v1(1662,1046)
  Top Layer w30: U3.3 1860.97,2256.03 K1.2 2125,1992 2169,1992 2245,1916 C11.2 2245,1797 2184.25,1736.25 VOUT2.6 VOUT2.4 VOUT2.2
  Bottom Layer w20: v2(946,1756) 1269,1756 1628,1397 1832.17,1397 1975.17,1254 ; v1(1662,1046) 1592,1116 v1(1592,1127) 1719,1254 1975.17,1254 ; VOUT2.2 1975.17,1254
VUSB: R9.2 USB.1 | length 1128.9
  Top Layer w30: v2(1229,2162) 1229,2099 1270,2058 1270,2025.95 USB.1 ; R9.2 v2(2011,1955)
  Bottom Layer w30: v2@1227,2162.31 1752.69,2162.31 1960,1955 v2(2011,1955)
WKUP: KEY_UP.2 U1.10 | length 1608.4
  Top Layer w6: U1.10 1154.1,1098.1 v1(1157,1101)
  Bottom Layer w6: v1(1157,1101) 1158,1100 1230,1100 1537,793 v1(1537,714) 1540.24,710.76 1931.24,710.76 2036.73,605.27 2036.73,550.76 KEY_UP.2@2292.64,550.76
XTALA: C9.2 R12.2 U1.5 Y2.1 | length 696.7
  Top Layer w6: Y2.1 578,920 C9.2 759.06,920 R12.2 842.06,1129.06 909.53,1196.53 U1.5
XTALB: C10.2 R12.1 U1.6 Y2.2 | length 747.9
  Top Layer w6: Y2.2 712.19,794.87 C10.2 832.06,913 R12.1 881,951.94 881,1136.97 920.87,1176.84 U1.6
XTALC: C7.2 U1.3 Y3.1 | length 570.1
  Top Layer w6: Y3.1 527,1379 548,1358 688.06,1358 715.06,1385 864.17,1235.9 U1.3 U1.3@992.87,1237.21
XTALD: C8.2 U1.4 Y3.2 | length 548.2
  Top Layer w6: Y3.2 554,1323 675,1323 707.94,1290.06 707.94,1245 802,1245 833,1214 989.34,1214 U1.4
pads on no net: JTAG.11 JTAG.17 JTAG.19 K1.1 K1.4 K1.5 K1.6 U1.2 U1.11 U1.18 U1.19 U1.25 U1.26 U1.27 U1.28 U1.29 U1.41 U2.9 U2.10 U2.11 U2.12 U2.15 U4.5 USB.4 USB.6 USB.7 USB.8 USB.9 USB.MH1 USB.MH2

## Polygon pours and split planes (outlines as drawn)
no net on Keep-Out Layer "Top Layer-No Net" (none, remove dead copper): 0,0 2362.2,0 2362.2,2362.21 0,2362.21
GND on Bottom Layer "Top Layer-No Net" (hatched 90Degree grid 4 track 5, remove dead copper, pour order 4): 0,0 2362.21,0 2362.21,2362.2 0,2362.2 0,0
GND on Top Layer "Top Layer-No Net" (hatched 90Degree grid 4 track 5, remove dead copper, pour order 5): 0,0 2362.2,0 2362.2,2362.2 0,2362.2 0,0

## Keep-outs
Keep-Out Layer:
  the board outline again, w10

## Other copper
Top Layer:
  rectangle net VUSB: 1247,1968 1306,2060
  pour cut-out: 967.84,1811.02 1417.32,1811.02 1411.5,1805.2 1411.5,1681 973.34,1681 967.84,1686.5
  pour cut-out: 944.88,1617.8 956.88,1605.8 1386.53,1605.8 1386.53,1504.64 1377.95,1496.06 959.84,1496.06 959.84,1602.17 947.84,1614.17
  pour cut-out: 1102.36,577.8 1106.36,573.8 1299.21,573.8 1299.21,473.07 1299.84,472.44 1095.84,472.44 1095.84,571.28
